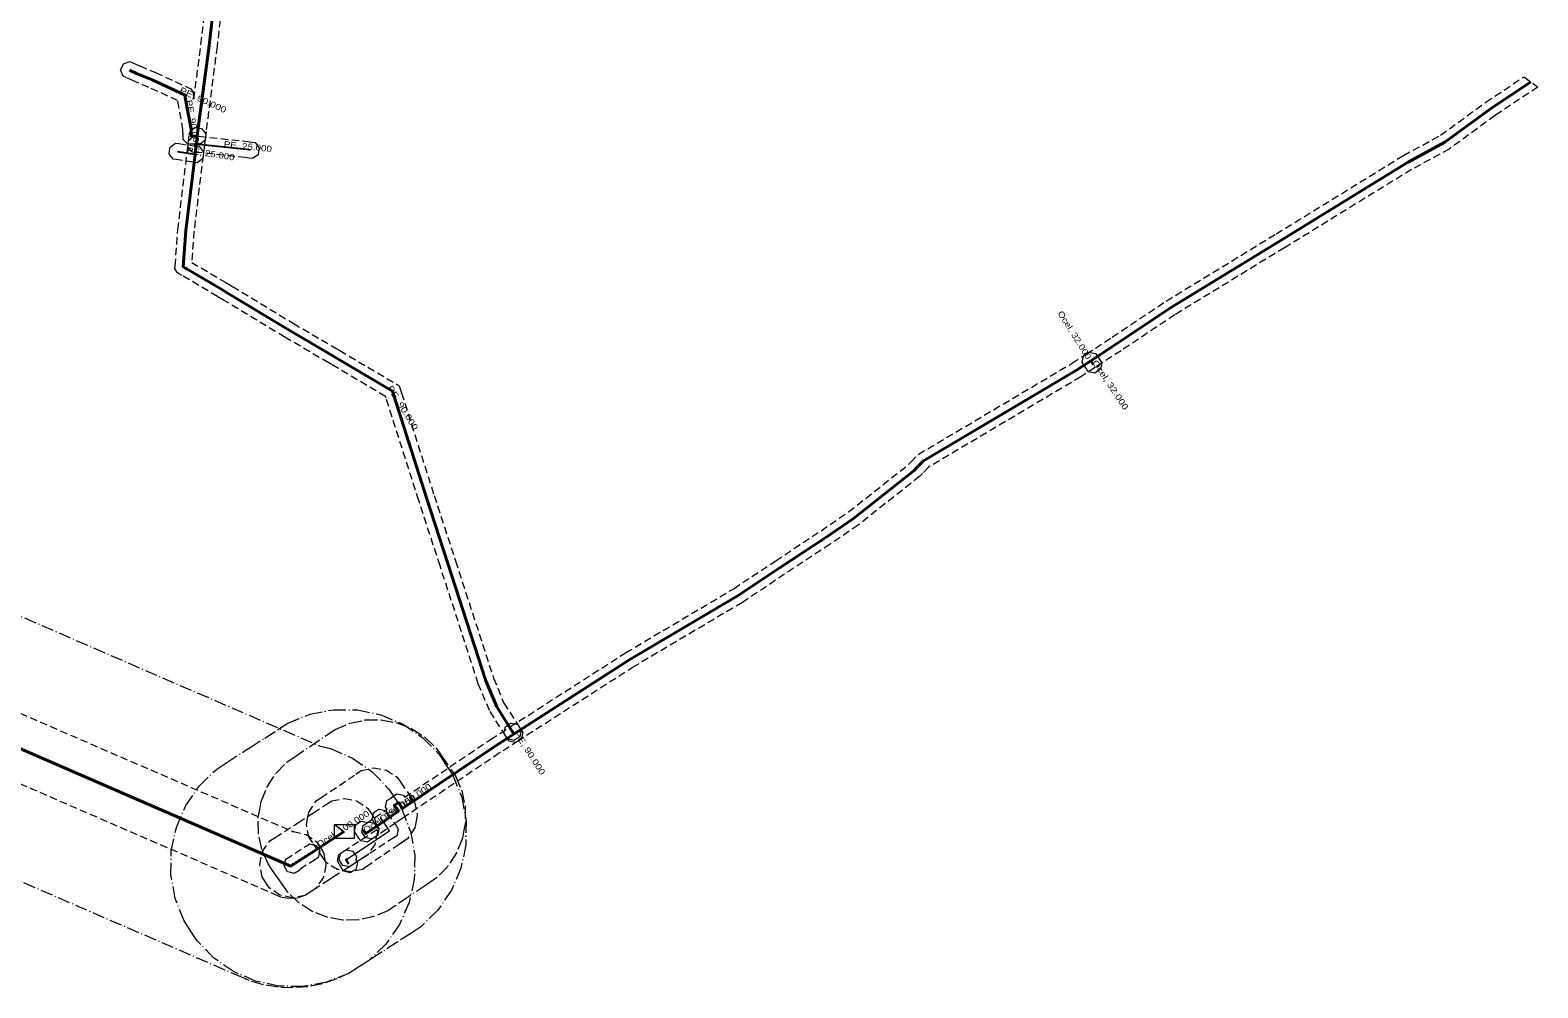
# Model space of a CAD drawing. Extents: x -640775 to -624586, y -1148563 to -1138811.
# Drawn here: x -625539.3 to -625353.5, y -1147645.4 to -1147527.3 of the extents above; entities that cross this region are included whole.
import ezdxf
from ezdxf.enums import TextEntityAlignment as Align

# ---------------------------------------------------------------- set-up
doc = ezdxf.new("R2010")
doc.units = 0
doc.header["$LTSCALE"] = 0.3
for name, pattern in [('DOT_DASHED', [7.7, 5, -1.2, 0.3, -1.2]), ('DOTTED', [1.5, 0.3, -1.2]), ('LONG_DASH_SHORT_DASH', [9.9, 6, -1.2, 1.5, -1.2]), ('MEDIUM_DASHED', [4.5, 3, -1.5])]:
    doc.linetypes.add(name, pattern=pattern)
for name, color, linetype, lineweight in [('1', 7, 'MEDIUM_DASHED', 13), ('10', 7, 'MEDIUM_DASHED', 13), ('24', 7, 'Continuous', 40), ('3', 7, 'DOT_DASHED', 13), ('31', 7, 'Continuous', 13), ('34', 7, 'Continuous', 40), ('55', 7, 'LONG_DASH_SHORT_DASH', 25), ('56', 7, 'DOTTED', 35), ('58', 7, 'Continuous', 13), ('7', 7, 'MEDIUM_DASHED', 13), ('8', 7, 'MEDIUM_DASHED', 13)]:
    doc.layers.add(name, color=color, linetype=linetype, lineweight=lineweight)
doc.layers.add('30', color=7, linetype='Continuous')
doc.layers.add('40', color=7, linetype='Continuous')

msp = doc.modelspace()

# ---------------------------------------------------------------- linework, layer by layer
at = {"layer": '1'}
for points in [[(-625515.271, -1147520.666), (-625516.288, -1147529.293), (-625517.648, -1147539.794), (-625517.727, -1147540.459), (-625517.773, -1147540.84), (-625518.35, -1147541.345), (-625518.734, -1147541.34), (-625519.474, -1147541.33), (-625519.874, -1147541.325), (-625520.445, -1147540.765), (-625520.459, -1147540.365), (-625520.487, -1147539.588), (-625521.145, -1147535.966), (-625524.694, -1147534.335), (-625526.6, -1147533.526), (-625527.5, -1147533.122), (-625527.878, -1147532.952), (-625528.172, -1147532.178), (-625528.002, -1147531.8), (-625527.832, -1147531.422), (-625527.058, -1147531.128), (-625526.68, -1147531.298), (-625525.8, -1147531.694), (-625523.886, -1147532.505), (-625519.802, -1147534.381), (-625519.554, -1147534.495), (-625519.242, -1147534.946), (-625519.223, -1147535.219), (-625519.206, -1147535.445), (-625519.145, -1147535.783), (-625518.272, -1147529.047), (-625517.257, -1147520.432)], [(-625729.508, -1147529.511), (-625657.697, -1147560.681), (-625567.808, -1147599.691), (-625506.903, -1147626.119), (-625506.869, -1147626.113), (-625505.315, -1147626.454), (-625504.01, -1147627.364), (-625503.581, -1147628.034), (-625503.152, -1147628.704), (-625502.873, -1147630.271), (-625503.214, -1147631.825), (-625504.124, -1147633.13), (-625504.794, -1147633.559), (-625505.044, -1147633.719), (-625505.458, -1147633.984), (-625506.39, -1147634.298), (-625507.371, -1147634.376), (-625508.341, -1147634.215), (-625508.792, -1147634.019), (-625570.992, -1147607.029), (-625660.883, -1147568.019), (-625732.692, -1147536.849)]]:
    msp.add_lwpolyline(points, dxfattribs=at)
for points in [[(-625355.231, -1147533.041), (-625353.51, -1147534.299), (-625358.777, -1147537.8), (-625364.423, -1147541.936), (-625369.068, -1147544.465), (-625384.727, -1147554.112), (-625398.241, -1147562.373), (-625404.87, -1147566.805), (-625408.075, -1147568.888), (-625409.842, -1147570.039), (-625428.613, -1147581.171), (-625429.357, -1147581.946), (-625429.705, -1147582.311), (-625437.277, -1147588.306), (-625440.722, -1147590.66), (-625446.337, -1147594.373), (-625451.547, -1147597.847), (-625464.885, -1147605.751), (-625479.146, -1147614.912), (-625481.47, -1147616.405), (-625492.861, -1147624.079), (-625493.058, -1147624.212), (-625493.06, -1147624.221), (-625493.404, -1147624.451), (-625494.165, -1147624.961), (-625494.308, -1147625.057), (-625496.824, -1147626.784), (-625497.165, -1147627.018), (-625497.98, -1147626.867), (-625498.214, -1147626.526), (-625498.448, -1147626.185), (-625498.297, -1147625.37), (-625497.956, -1147625.136), (-625495.432, -1147623.403), (-625495.342, -1147623.343), (-625495.511, -1147623.084), (-625495.35, -1147622.282), (-625495.012, -1147622.053), (-625494.482, -1147621.693), (-625494.14, -1147621.461), (-625493.328, -1147621.614), (-625493.156, -1147621.866), (-625482.57, -1147614.735), (-625480.228, -1147613.23), (-625465.935, -1147604.049), (-625452.613, -1147596.153), (-625447.443, -1147592.707), (-625441.838, -1147589), (-625438.463, -1147586.694), (-625431.055, -1147580.829), (-625430.801, -1147580.564), (-625429.867, -1147579.589), (-625410.898, -1147568.341), (-625409.165, -1147567.212), (-625405.97, -1147565.135), (-625399.319, -1147560.687), (-625385.773, -1147552.408), (-625370.072, -1147542.735), (-625365.497, -1147540.244), (-625359.923, -1147536.16)], [(-625518.001, -1147542.72), (-625519.134, -1147552.066), (-625519.413, -1147555.912), (-625515.2, -1147558.41), (-625514.386, -1147558.892), (-625506.898, -1147563.431), (-625501.514, -1147566.588), (-625501.172, -1147566.789), (-625493.842, -1147571.124), (-625493.597, -1147571.896), (-625493.561, -1147572.01), (-625489.528, -1147584.663), (-625486.899, -1147592.721), (-625482.211, -1147607.183), (-625480.93, -1147610.256), (-625479.016, -1147613.263), (-625478.794, -1147613.613), (-625478.973, -1147614.422), (-625479.323, -1147614.644), (-625479.673, -1147614.866), (-625480.482, -1147614.687), (-625480.704, -1147614.337), (-625482.71, -1147611.184), (-625484.089, -1147607.877), (-625488.801, -1147593.339), (-625491.432, -1147585.277), (-625495.465, -1147572.62), (-625495.503, -1147572.504), (-625495.518, -1147572.456), (-625502.188, -1147568.511), (-625502.526, -1147568.312), (-625507.922, -1147565.149), (-625515.414, -1147560.608), (-625516.22, -1147560.13), (-625520.587, -1147557.541), (-625520.69, -1147557.48), (-625520.965, -1147557.317), (-625521.209, -1147557.172), (-625521.473, -1147556.669), (-625521.452, -1147556.385), (-625521.126, -1147551.874), (-625519.987, -1147542.48), (-625519.836, -1147541.237), (-625519.713, -1147540.22), (-625519.663, -1147539.809), (-625519.011, -1147539.297), (-625518.6, -1147539.347), (-625518.189, -1147539.397), (-625517.677, -1147540.049), (-625517.727, -1147540.46), (-625517.85, -1147541.477)], [(-625511.232, -1147542.643), (-625511.906, -1147543.124), (-625512.314, -1147543.056), (-625512.764, -1147542.981), (-625518.656, -1147542.368), (-625518.842, -1147542.359), (-625518.9, -1147542.355), (-625519.313, -1147542.332), (-625519.865, -1147541.714), (-625519.841, -1147541.3), (-625519.818, -1147540.887), (-625519.2, -1147540.335), (-625518.786, -1147540.359), (-625518.738, -1147540.361), (-625518.504, -1147540.372), (-625512.496, -1147540.999), (-625511.986, -1147541.084), (-625511.577, -1147541.152), (-625511.096, -1147541.826), (-625511.164, -1147542.234)], [(-625522.073, -1147541.695), (-625521.403, -1147541.207), (-625520.994, -1147541.272), (-625518.907, -1147541.602), (-625518.844, -1147541.611), (-625518.434, -1147541.673), (-625517.943, -1147542.34), (-625518.005, -1147542.75), (-625518.067, -1147543.16), (-625518.734, -1147543.651), (-625519.144, -1147543.589), (-625519.213, -1147543.578), (-625521.306, -1147543.248), (-625521.715, -1147543.183), (-625522.203, -1147542.513), (-625522.138, -1147542.104)], [(-625408.83, -1147566.988), (-625408.018, -1147567.15), (-625407.788, -1147567.495), (-625407.488, -1147567.945), (-625407.258, -1147568.29), (-625407.42, -1147569.102), (-625407.765, -1147569.332), (-625408.11, -1147569.562), (-625408.922, -1147569.4), (-625409.152, -1147569.055), (-625409.452, -1147568.605), (-625409.682, -1147568.26), (-625409.52, -1147567.448), (-625409.175, -1147567.218)], [(-625480.049, -1147612.734), (-625479.24, -1147612.913), (-625479.017, -1147613.262), (-625478.844, -1147613.533), (-625478.621, -1147613.882), (-625478.8, -1147614.691), (-625479.149, -1147614.914), (-625479.498, -1147615.137), (-625480.307, -1147614.958), (-625480.53, -1147614.609), (-625480.703, -1147614.338), (-625480.926, -1147613.989), (-625480.747, -1147613.18), (-625480.398, -1147612.957)], [(-625510.694, -1147628.572), (-625509.789, -1147627.263), (-625509.121, -1147626.831), (-625506.835, -1147625.353), (-625506.259, -1147624.979), (-625504.423, -1147623.801), (-625502.796, -1147622.74), (-625502.13, -1147622.305), (-625500.566, -1147622.012), (-625499.008, -1147622.339), (-625497.695, -1147623.238), (-625497.26, -1147623.904), (-625496.825, -1147624.57), (-625496.532, -1147626.134), (-625496.859, -1147627.692), (-625497.758, -1147629.005), (-625498.424, -1147629.44), (-625500.077, -1147630.519), (-625501.921, -1147631.701), (-625502.485, -1147632.067), (-625504.779, -1147633.549), (-625505.447, -1147633.981), (-625507.012, -1147634.268), (-625508.568, -1147633.934), (-625509.877, -1147633.029), (-625510.309, -1147632.361), (-625510.741, -1147631.693), (-625511.028, -1147630.128)], [(-625498.859, -1147625.041), (-625498.515, -1147624.809), (-625497.71, -1147624.966), (-625497.617, -1147624.902), (-625496.802, -1147625.051), (-625496.567, -1147625.392), (-625496.332, -1147625.733), (-625496.481, -1147626.548), (-625496.822, -1147626.783), (-625497.402, -1147627.183), (-625497.746, -1147627.42), (-625498.156, -1147627.343), (-625498.566, -1147627.265), (-625498.799, -1147626.919), (-625499.129, -1147626.429), (-625499.361, -1147626.085), (-625499.202, -1147625.272)]]:
    msp.add_lwpolyline(points, close=True, dxfattribs=at)
at = {"layer": '1', "linetype": 'DOT_DASHED'}
msp.add_lwpolyline([(-625563.429, -1147589.6), (-625503.569, -1147615.575), (-625502.291, -1147615.855), (-625499.584, -1147617.04), (-625497.16, -1147618.73), (-625495.112, -1147620.86), (-625494.316, -1147622.104), (-625493.52, -1147623.348), (-625492.443, -1147626.1), (-625491.924, -1147629.009), (-625491.982, -1147631.963), (-625492.615, -1147634.849), (-625493.8, -1147637.556), (-625495.49, -1147639.98), (-625497.62, -1147642.028), (-625498.864, -1147642.824), (-625499.114, -1147642.984), (-625499.888, -1147643.479), (-625501.545, -1147644.273), (-625503.286, -1147644.859), (-625505.086, -1147645.228), (-625506.918, -1147645.375), (-625508.754, -1147645.297), (-625510.566, -1147644.996), (-625512.328, -1147644.476), (-625513.171, -1147644.11), (-625575.371, -1147617.12)], dxfattribs=at)
msp.add_lwpolyline([(-625518.454, -1147620.451), (-625516.333, -1147618.394), (-625515.092, -1147617.592), (-625512.815, -1147616.12), (-625512.222, -1147615.736), (-625510.397, -1147614.565), (-625508.806, -1147613.527), (-625507.569, -1147612.72), (-625504.827, -1147611.619), (-625501.923, -1147611.075), (-625498.968, -1147611.107), (-625496.077, -1147611.715), (-625493.359, -1147612.876), (-625490.921, -1147614.544), (-625488.854, -1147616.657), (-625488.047, -1147617.894), (-625487.24, -1147619.131), (-625486.139, -1147621.873), (-625485.595, -1147624.777), (-625485.627, -1147627.732), (-625486.235, -1147630.623), (-625487.396, -1147633.341), (-625489.064, -1147635.779), (-625491.177, -1147637.846), (-625492.414, -1147638.653), (-625494.103, -1147639.755), (-625495.958, -1147640.944), (-625496.505, -1147641.3), (-625498.808, -1147642.788), (-625500.049, -1147643.59), (-625502.796, -1147644.679), (-625505.702, -1147645.211), (-625508.656, -1147645.166), (-625511.545, -1147644.545), (-625514.258, -1147643.373), (-625516.689, -1147641.694), (-625518.746, -1147639.573), (-625519.548, -1147638.332), (-625520.35, -1147637.091), (-625521.439, -1147634.344), (-625521.971, -1147631.438), (-625521.926, -1147628.484), (-625521.305, -1147625.595), (-625520.133, -1147622.882)], close=True, dxfattribs=at)
at = {"layer": '10'}
msp.add_lwpolyline([(-625501.24, -1147629.607), (-625501.073, -1147628.795), (-625500.727, -1147628.568), (-625496.414, -1147625.73), (-625496.94, -1147624.948), (-625497.171, -1147624.605), (-625497.012, -1147623.792), (-625496.668, -1147623.56), (-625496.325, -1147623.329), (-625495.512, -1147623.488), (-625495.28, -1147623.832), (-625494.19, -1147625.452), (-625493.957, -1147625.798), (-625494.04, -1147626.207), (-625494.122, -1147626.616), (-625494.47, -1147626.845), (-625499.627, -1147630.238), (-625499.973, -1147630.466), (-625500.785, -1147630.299), (-625501.012, -1147629.953)], close=True, dxfattribs=at)
at = {"layer": '24', "lineweight": 25}
msp.add_line((-625408.62, -1147568.05), (-625408.32, -1147568.5), dxfattribs=at)
at = {"layer": '24'}
msp.add_line((-625479.86, -1147613.8), (-625479.687, -1147614.071), dxfattribs=at)
for points in [[(-625516.264, -1147520.549), (-625517.28, -1147529.17), (-625518.64, -1147539.67), (-625518.72, -1147540.34)], [(-625518.72, -1147540.34), (-625519.46, -1147540.33), (-625519.49, -1147539.48), (-625520.2, -1147535.57), (-625520.22, -1147535.29), (-625524.29, -1147533.42), (-625526.2, -1147532.61), (-625527.09, -1147532.21)], [(-625354.371, -1147533.67), (-625359.35, -1147536.98), (-625364.96, -1147541.09), (-625369.57, -1147543.6), (-625385.25, -1147553.26), (-625398.78, -1147561.53), (-625405.42, -1147565.97), (-625408.62, -1147568.05)], [(-625518.72, -1147540.34), (-625518.843, -1147541.357), (-625518.994, -1147542.6)], [(-625518.994, -1147542.6), (-625520.13, -1147551.97), (-625520.455, -1147556.457), (-625520.18, -1147556.62), (-625520.077, -1147556.681), (-625515.71, -1147559.27)], [(-625515.71, -1147559.27), (-625514.9, -1147559.75), (-625507.41, -1147564.29), (-625502.02, -1147567.45)], [(-625502.02, -1147567.45), (-625501.68, -1147567.65), (-625494.68, -1147571.79), (-625494.55, -1147572.2), (-625494.513, -1147572.315)], [(-625408.62, -1147568.05), (-625410.37, -1147569.19), (-625429.24, -1147580.38), (-625430.079, -1147581.255), (-625430.38, -1147581.57)], [(-625494.513, -1147572.315), (-625490.48, -1147584.97), (-625487.85, -1147593.03), (-625483.15, -1147607.53), (-625481.82, -1147610.72), (-625479.86, -1147613.8)], [(-625430.38, -1147581.57), (-625437.87, -1147587.5), (-625441.28, -1147589.83), (-625446.89, -1147593.54), (-625452.08, -1147597), (-625465.41, -1147604.9), (-625479.687, -1147614.071)], [(-625479.687, -1147614.071), (-625482.02, -1147615.57), (-625493.42, -1147623.25), (-625493.92, -1147622.52), (-625494.45, -1147622.88), (-625494.3, -1147623.11)], [(-625494.723, -1147624.131), (-625494.87, -1147624.23), (-625497.39, -1147625.96)], [(-625494.3, -1147623.11), (-625493.96, -1147623.62), (-625494.723, -1147624.131)], [(-625497.39, -1147625.96), (-625497.97, -1147626.36), (-625498.3, -1147625.87)]]:
    msp.add_lwpolyline(points, dxfattribs=at)
at = {"layer": '24', "lineweight": 25}
for points in [[(-625521.15, -1147542.26), (-625519.06, -1147542.59), (-625518.994, -1147542.6)], [(-625512.15, -1147542.07), (-625512.63, -1147541.99), (-625518.58, -1147541.37), (-625518.79, -1147541.36), (-625518.843, -1147541.357)]]:
    msp.add_lwpolyline(points, dxfattribs=at)
at = {"layer": '3'}
msp.add_lwpolyline([(-625490.666, -1147614.474), (-625489.26, -1147615.839), (-625488.703, -1147616.645), (-625487.473, -1147618.425), (-625486.911, -1147619.238), (-625486.127, -1147621.053), (-625485.714, -1147622.986), (-625485.688, -1147624.962), (-625485.868, -1147625.934), (-625486.048, -1147626.906), (-625486.783, -1147628.741), (-625487.862, -1147630.398), (-625489.244, -1147631.811), (-625490.06, -1147632.368), (-625490.483, -1147632.656), (-625492.679, -1147634.147), (-625494.346, -1147635.28), (-625495.153, -1147635.829), (-625496.95, -1147636.593), (-625498.861, -1147636.996), (-625500.814, -1147637.021), (-625502.734, -1147636.668), (-625504.55, -1147635.951), (-625506.193, -1147634.895), (-625507.601, -1147633.542), (-625508.161, -1147632.742), (-625508.83, -1147631.785), (-625509.446, -1147630.887), (-625510.005, -1147630.072), (-625510.782, -1147628.256), (-625511.189, -1147626.322), (-625511.21, -1147624.347), (-625511.027, -1147623.376), (-625510.844, -1147622.405), (-625510.104, -1147620.573), (-625509.021, -1147618.92), (-625507.635, -1147617.512), (-625506.818, -1147616.957), (-625502.548, -1147614.057), (-625501.737, -1147613.507), (-625499.933, -1147612.741), (-625498.015, -1147612.341), (-625496.056, -1147612.32), (-625494.129, -1147612.68), (-625492.31, -1147613.407)], close=True, dxfattribs=at)
at = {"layer": '3', "linetype": 'MEDIUM_DASHED'}
msp.add_lwpolyline([(-625495.417, -1147618.544), (-625494.089, -1147619.405), (-625493.639, -1147620.056), (-625492.409, -1147621.836), (-625491.955, -1147622.493), (-625491.622, -1147624.055), (-625491.767, -1147624.84), (-625491.913, -1147625.625), (-625492.785, -1147626.963), (-625493.444, -1147627.413), (-625493.859, -1147627.697), (-625496.05, -1147629.183), (-625497.719, -1147630.317), (-625498.371, -1147630.76), (-625499.914, -1147631.085), (-625501.465, -1147630.8), (-625502.792, -1147629.948), (-625503.244, -1147629.302), (-625503.898, -1147628.368), (-625504.498, -1147627.493), (-625504.95, -1147626.835), (-625505.279, -1147625.273), (-625505.131, -1147624.489), (-625504.983, -1147623.705), (-625504.108, -1147622.369), (-625503.447, -1147621.921), (-625499.177, -1147619.021), (-625498.522, -1147618.576), (-625496.973, -1147618.253)], close=True, dxfattribs=at)
at = {"layer": '31'}
msp.add_lwpolyline([(-625501.835, -1147625.224), (-625499.385, -1147625.224), (-625499.385, -1147626.956), (-625501.835, -1147626.956)], dxfattribs=at)
msp.add_lwpolyline([(-625501.835, -1147625.224), (-625500.61, -1147626.09), (-625501.835, -1147626.956)], close=True, dxfattribs=at)
at = {"layer": '34'}
for points in [[(-625826.98, -1147491.58), (-625731.1, -1147533.18), (-625659.29, -1147564.35), (-625569.4, -1147603.36), (-625507.2, -1147630.35), (-625506.95, -1147630.19)], [(-625506.95, -1147630.19), (-625504.66, -1147628.71), (-625504.09, -1147628.34), (-625502.25, -1147627.16), (-625500.61, -1147626.09)]]:
    msp.add_lwpolyline(points, dxfattribs=at)
at = {"layer": '55'}
msp.add_lwpolyline([(-625500.052, -1147630.127), (-625500.4, -1147629.55), (-625500.177, -1147629.403)], dxfattribs=at)
at = {"layer": '56'}
msp.add_lwpolyline([(-625506.95, -1147630.19), (-625506.934, -1147630.129), (-625504.702, -1147628.691)], dxfattribs=at)
at = {"layer": '58'}
msp.add_lwpolyline([(-625500.177, -1147629.403), (-625495.02, -1147626.01), (-625496.11, -1147624.39)], dxfattribs=at)
at = {"layer": '7'}
msp.add_lwpolyline([(-625499.342, -1147628.853), (-625499.114, -1147629.199), (-625499.198, -1147629.607), (-625499.196, -1147629.611), (-625498.982, -1147629.966), (-625499.181, -1147630.769), (-625499.536, -1147630.983), (-625499.891, -1147631.197), (-625500.694, -1147630.998), (-625500.908, -1147630.643), (-625501.256, -1147630.066), (-625501.464, -1147629.722), (-625501.286, -1147628.937), (-625500.95, -1147628.715), (-625500.727, -1147628.568), (-625500.381, -1147628.34), (-625499.57, -1147628.507)], close=True, dxfattribs=at)
at = {"layer": '8'}
msp.add_lwpolyline([(-625503.812, -1147629.307), (-625504.16, -1147629.532), (-625506.066, -1147630.76), (-625506.088, -1147630.845), (-625506.803, -1147631.262), (-625507.204, -1147631.157), (-625507.605, -1147631.052), (-625508.022, -1147630.337), (-625507.917, -1147629.936), (-625507.803, -1147629.499), (-625505.244, -1147627.85), (-625504.896, -1147627.626), (-625504.086, -1147627.801), (-625503.861, -1147628.149), (-625503.637, -1147628.497)], close=True, dxfattribs=at)

# ---------------------------------------------------------------- texts
at = {"layer": '30'}
for s, rotation, width, p in [('PE, 90.000', 335.323, 1.25, (-625520.985, -1147534.938)), ('PE, 90.000', 280.292, 1.2, (-625520.128, -1147535.966)), ('PE, 25.000', 354.051, 1.2, (-625515.494, -1147541.692)), ('PE, 25.000', 351.027, 1.2, (-625520.072, -1147542.43)), ('Ocel, 32.000', 303.69, 1.25, (-625408.47, -1147568.275)), ('PE, 90.000', 301.574, 1.25, (-625495.345, -1147571.397)), ('PE, 90.000', 302.553, 1.25, (-625479.747, -1147613.978)), ('Ocel, 150.000', 34.47, 1.2, (-625495.96, -1147624.978)), ('Ocel, 150.000', 34.592, 1.2, (-625497.964, -1147626.356))]:
    msp.add_text(s, height=0.75, rotation=rotation, dxfattribs=dict(at, width=width)).set_placement(p)
at = {"layer": '30', "width": 1.2}
msp.add_text('Ocel, 32.000', height=0.75, rotation=301.949, dxfattribs=at).set_placement((-625410.924, -1147565.076), align=Align.CENTER)
at = {"layer": '40', "width": 1.2}
msp.add_text('Ocel, 100.000', height=0.75, rotation=32.672, dxfattribs=at).set_placement((-625503.737, -1147628.114))

doc.saveas('drawing.dxf')
